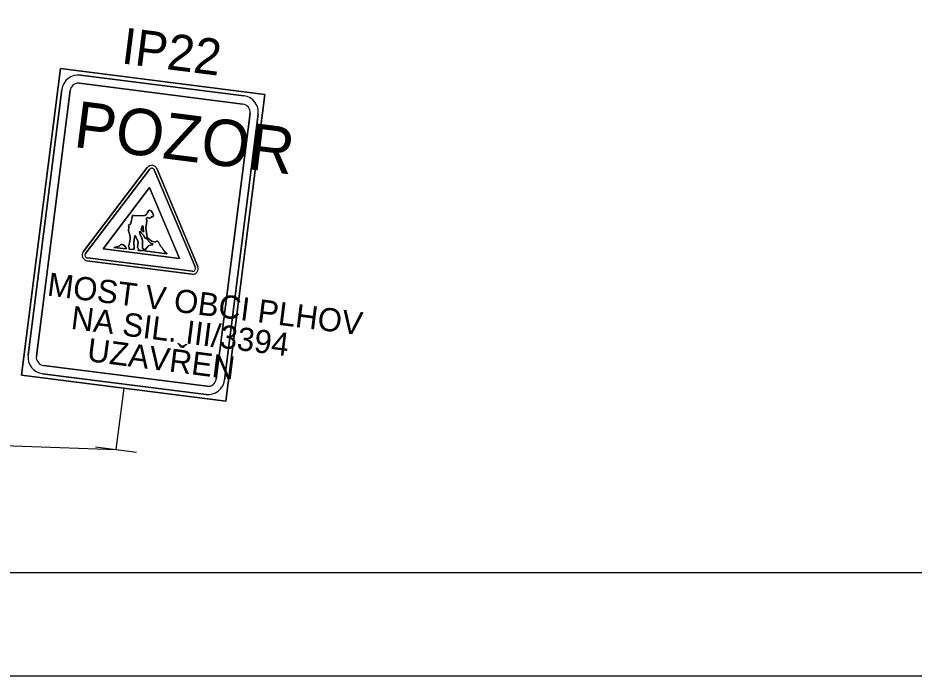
# Model space of a CAD drawing. Extents: x -688893 to -679983, y -1088371 to -1075771.
# Drawn here: x -685743 to -684438, y -1088371 to -1087413 of the extents above; entities that cross this region are included whole.
import ezdxf

# ---------------------------------------------------------------- set-up
doc = ezdxf.new("R2010")
doc.units = 0
for name, color, linetype in [('ramecek', 7, 'Continuous'), ('SDZ', 7, 'Continuous'), ('SDZ ozn', 7, 'Continuous'), ('SDZ plochy', 7, 'Continuous'), ('SDZ symbol', 7, 'Continuous')]:
    doc.layers.add(name, color=color, linetype=linetype)

msp = doc.modelspace()

# ---------------------------------------------------------------- linework, layer by layer
at = {"layer": 'ramecek'}
for points in [[(-679983.4, -1075770.7), (-679983.4, -1088370.7), (-688893.4, -1088370.7), (-688893.4, -1075770.7)], [(-680133.4, -1076070.7), (-680133.4, -1088220.7), (-688743.4, -1088220.7), (-688743.4, -1076070.7)]]:
    msp.add_lwpolyline(points, close=True, dxfattribs=at)
at = {"layer": 'SDZ'}
for p, q in [((-685737.5, -1087932.7), (-685680.8, -1087486.3)), ((-685680.8, -1087486.3), (-685383.2, -1087524.1)), ((-685651.8, -1087496), (-685413.7, -1087526.3)), ((-685727.8, -1087903.7), (-685678.7, -1087516.8)), ((-685715.9, -1087905.2), (-685666.8, -1087518.3)), ((-685653.3, -1087507.9), (-685415.3, -1087538.2)), ((-685383.2, -1087524.1), (-685439.9, -1087970.5)), ((-685404.9, -1087551.6), (-685454, -1087938.5)), ((-685393, -1087553.1), (-685442.1, -1087940)), ((-685647.6, -1087753.3), (-685554.4, -1087630.5)), ((-685551.2, -1087633.2), (-685644.4, -1087755.7)), ((-685551.1, -1087633.1), (-685551.1, -1087633.1)), ((-685484.5, -1087776), (-685544.2, -1087634)), ((-685540.4, -1087632.2), (-685480.8, -1087774.5)), ((-685540.4, -1087632.4), (-685540.4, -1087632.4)), ((-685551, -1087659.6), (-685618.8, -1087748.8)), ((-685507.6, -1087762.9), (-685551, -1087659.6)), ((-685575.8, -1087700.5), (-685578.4, -1087711.8)), ((-685574.3, -1087700.3), (-685575.8, -1087700.5)), ((-685560.7, -1087701), (-685574.3, -1087700.3)), ((-685557.8, -1087700.4), (-685560.7, -1087701)), ((-685555.5, -1087698.8), (-685557.8, -1087700.4)), ((-685554, -1087696), (-685555.5, -1087698.8)), ((-685552.2, -1087693.3), (-685554, -1087696)), ((-685550.5, -1087692.5), (-685552.2, -1087693.3)), ((-685548.6, -1087693.8), (-685550.5, -1087692.5)), ((-685549, -1087703.1), (-685547.8, -1087701.9)), ((-685546.7, -1087696.5), (-685548.6, -1087693.8)), ((-685547.8, -1087701.9), (-685546.8, -1087702.2)), ((-685546.8, -1087702.2), (-685545.7, -1087701.7)), ((-685545.3, -1087699.7), (-685546.7, -1087696.5)), ((-685545.7, -1087701.7), (-685545.3, -1087699.7)), ((-685578.4, -1087711.8), (-685581.7, -1087714.9)), ((-685581.7, -1087714.9), (-685581.1, -1087716.4)), ((-685556.4, -1087718.1), (-685555.8, -1087711.9)), ((-685555.8, -1087711.9), (-685555.3, -1087708)), ((-685555.7, -1087704.5), (-685554.7, -1087703.4)), ((-685555.4, -1087705.6), (-685555.7, -1087704.5)), ((-685555.3, -1087708), (-685555.4, -1087705.6)), ((-685554.7, -1087703.4), (-685553.9, -1087703.5)), ((-685553.9, -1087703.5), (-685552.4, -1087704.3)), ((-685552.4, -1087704.3), (-685550.5, -1087704.2)), ((-685550.5, -1087704.2), (-685549, -1087703.1)), ((-685581.1, -1087716.4), (-685582, -1087722.6)), ((-685582, -1087722.6), (-685581, -1087725.8)), ((-685581, -1087725.8), (-685579.6, -1087730.9)), ((-685565.6, -1087723.7), (-685565.2, -1087723.3)), ((-685564.8, -1087728.3), (-685565.6, -1087723.7)), ((-685565.2, -1087723.3), (-685560.2, -1087728.9)), ((-685563.1, -1087719.3), (-685563.4, -1087720.7)), ((-685563.4, -1087720.7), (-685562.6, -1087722.4)), ((-685562, -1087715.8), (-685563.1, -1087719.3)), ((-685562.6, -1087722.4), (-685560.2, -1087724.4)), ((-685561.1, -1087715.3), (-685562, -1087715.8)), ((-685560.6, -1087716.3), (-685561.1, -1087715.3)), ((-685560.4, -1087719.4), (-685560.6, -1087716.3)), ((-685560, -1087722.8), (-685560.4, -1087719.4)), ((-685560.2, -1087724.4), (-685560, -1087722.8)), ((-685555.7, -1087725.5), (-685556.4, -1087718.1)), ((-685554.9, -1087729.1), (-685555.7, -1087725.5)), ((-685580.4, -1087740.4), (-685581.9, -1087745.9)), ((-685579.6, -1087735.4), (-685580.4, -1087740.4)), ((-685579.6, -1087730.9), (-685579.6, -1087735.4)), ((-685574.1, -1087738.5), (-685573.3, -1087732.5)), ((-685573.7, -1087748.2), (-685574.1, -1087738.5)), ((-685573.3, -1087732.5), (-685572.5, -1087729.5)), ((-685572.5, -1087729.5), (-685570.4, -1087732.5)), ((-685570.4, -1087732.5), (-685568.3, -1087737.8)), ((-685567.6, -1087739.3), (-685568.6, -1087746.8)), ((-685568.3, -1087737.8), (-685567.6, -1087739.3)), ((-685562.3, -1087733.1), (-685564.8, -1087728.3)), ((-685561.5, -1087737.5), (-685562.3, -1087733.1)), ((-685561.6, -1087743), (-685561.5, -1087737.5)), ((-685560.2, -1087728.9), (-685559.2, -1087730.8)), ((-685559.2, -1087730.8), (-685557.7, -1087733.5)), ((-685557.7, -1087733.5), (-685556.1, -1087733.7)), ((-685556.1, -1087733.7), (-685549.7, -1087740.8)), ((-685554.5, -1087730.8), (-685554.9, -1087729.1)), ((-685554.9, -1087732), (-685554.5, -1087730.8)), ((-685548.3, -1087737.9), (-685554.9, -1087732)), ((-685549.7, -1087740.8), (-685546.3, -1087741.8)), ((-685542.7, -1087739), (-685548.3, -1087737.9)), ((-685540.9, -1087737.8), (-685542.7, -1087739)), ((-685539.7, -1087737.6), (-685540.9, -1087737.8)), ((-685538.2, -1087739.4), (-685539.7, -1087737.6)), ((-685536.6, -1087742.3), (-685538.2, -1087739.4)), ((-685618.8, -1087748.8), (-685507.6, -1087762.9)), ((-685598.7, -1087745.8), (-685603.3, -1087747.1)), ((-685603.3, -1087747.1), (-685584.8, -1087749)), ((-685595.5, -1087745), (-685598.7, -1087745.8)), ((-685592.8, -1087742.7), (-685595.5, -1087745)), ((-685591.7, -1087742.4), (-685592.8, -1087742.7)), ((-685590.5, -1087742.6), (-685591.7, -1087742.4)), ((-685589.6, -1087743.3), (-685590.5, -1087742.6)), ((-685586.9, -1087745.1), (-685589.6, -1087743.3)), ((-685585.8, -1087747.2), (-685586.9, -1087745.1)), ((-685584.8, -1087749), (-685585.8, -1087747.2)), ((-685581.9, -1087745.9), (-685580.9, -1087747.2)), ((-685580.9, -1087747.2), (-685580.9, -1087749.3)), ((-685580.9, -1087749.3), (-685574.3, -1087749.9)), ((-685574.3, -1087749.9), (-685573.7, -1087748.2)), ((-685568.6, -1087746.8), (-685567.5, -1087747.9)), ((-685567.4, -1087749), (-685567.7, -1087751.2)), ((-685567.7, -1087751.2), (-685560, -1087751.5)), ((-685567.5, -1087747.9), (-685567.4, -1087749)), ((-685561.3, -1087747.7), (-685561.6, -1087743)), ((-685559.4, -1087748.7), (-685561.3, -1087747.7)), ((-685560, -1087751.5), (-685559.4, -1087750)), ((-685559.4, -1087750), (-685559.4, -1087748.7)), ((-685555.9, -1087748.4), (-685558.6, -1087751.9)), ((-685558.6, -1087751.9), (-685526.1, -1087756.2)), ((-685552.8, -1087744.7), (-685555.9, -1087748.4)), ((-685550.2, -1087743.6), (-685552.8, -1087744.7)), ((-685546.9, -1087743.2), (-685550.2, -1087743.6)), ((-685546.3, -1087741.8), (-685546.9, -1087743.2)), ((-685534.7, -1087745.6), (-685536.6, -1087742.3)), ((-685532.4, -1087747.9), (-685534.7, -1087745.6)), ((-685531.3, -1087750.5), (-685532.4, -1087747.9)), ((-685529.8, -1087751.7), (-685531.3, -1087750.5)), ((-685528.4, -1087753.7), (-685529.8, -1087751.7)), ((-685526.7, -1087754.5), (-685528.4, -1087753.7)), ((-685642.2, -1087766.2), (-685489.3, -1087785.6)), ((-685641.7, -1087762.2), (-685488.8, -1087781.6)), ((-685526.1, -1087756.2), (-685526.7, -1087754.5)), ((-685467.4, -1087948.9), (-685705.5, -1087918.6)), ((-685439.9, -1087970.5), (-685737.5, -1087932.7)), ((-685468.9, -1087960.8), (-685707, -1087930.6)), ((-685588.7, -1087951.6), (-685600.1, -1088040.9)), ((-685629.8, -1088037.1), (-685570.3, -1088044.7))]:
    msp.add_line(p, q, dxfattribs=at)
msp.add_lwpolyline([(-686579.3, -1088005.8), (-685600.1, -1088040.9)], dxfattribs=at)
for centre, radius, start, end in [((-685654.9, -1087519.9), 24, 82.7618, 172.7618), ((-685654.9, -1087519.9), 12, 82.7618, 172.7618), ((-685416.8, -1087550.1), 24, 352.7618, 82.7618), ((-685416.8, -1087550.1), 12, 352.7618, 82.7618), ((-685547.9, -1087635.4), 8.1, 22.7309, 142.7927), ((-685547.9, -1087635.6), 4.05, 22.7961, 142.7275), ((-685641.1, -1087758.2), 8.1, 142.7927, 262.7618), ((-685641.2, -1087758.2), 4.05, 142.7275, 262.7618), ((-685488.3, -1087777.6), 8.1, 262.7618, 22.7309), ((-685488.3, -1087777.6), 4.05, 262.7618, 22.7961), ((-685704, -1087906.7), 24, 172.7618, 262.7618), ((-685704, -1087906.7), 12, 172.7618, 262.7618), ((-685465.9, -1087937), 24, 262.7618, 352.7618), ((-685465.9, -1087937), 12, 262.7618, 352.7618)]:
    msp.add_arc(centre, radius, start, end, dxfattribs=at)
at = {"layer": 'SDZ plochy'}
for p, q in [((-685680.8, -1087486.3), (-685737.5, -1087932.7)), ((-685383.2, -1087524.1), (-685680.8, -1087486.3)), ((-685413.7, -1087526.3), (-685651.8, -1087496)), ((-685651.8, -1087496), (-685413.7, -1087526.3)), ((-685678.7, -1087516.8), (-685727.8, -1087903.7)), ((-685727.8, -1087903.7), (-685678.7, -1087516.8)), ((-685715.9, -1087905.2), (-685666.8, -1087518.3)), ((-685666.8, -1087518.3), (-685715.9, -1087905.2)), ((-685653.3, -1087507.9), (-685415.3, -1087538.2)), ((-685415.3, -1087538.2), (-685653.3, -1087507.9)), ((-685439.9, -1087970.5), (-685383.2, -1087524.1)), ((-685404.9, -1087551.6), (-685454, -1087938.5)), ((-685454, -1087938.5), (-685404.9, -1087551.6)), ((-685442.1, -1087940), (-685393, -1087553.1)), ((-685393, -1087553.1), (-685442.1, -1087940)), ((-685647.6, -1087753.3), (-685554.4, -1087630.5)), ((-685554.4, -1087630.5), (-685647.6, -1087753.3)), ((-685551.2, -1087633.2), (-685644.4, -1087755.7)), ((-685644.4, -1087755.7), (-685551.2, -1087633.2)), ((-685484.5, -1087776), (-685544.2, -1087634)), ((-685544.2, -1087634), (-685484.5, -1087776)), ((-685540.4, -1087632.2), (-685480.8, -1087774.5)), ((-685480.8, -1087774.5), (-685540.4, -1087632.2)), ((-685618.8, -1087748.8), (-685551, -1087659.6)), ((-685551, -1087659.6), (-685618.8, -1087748.8)), ((-685551, -1087659.6), (-685507.6, -1087762.9)), ((-685507.6, -1087762.9), (-685551, -1087659.6)), ((-685575.8, -1087700.5), (-685578.4, -1087711.8)), ((-685578.4, -1087711.8), (-685575.8, -1087700.5)), ((-685574.3, -1087700.3), (-685575.8, -1087700.5)), ((-685575.8, -1087700.5), (-685574.3, -1087700.3)), ((-685560.7, -1087701), (-685574.3, -1087700.3)), ((-685574.3, -1087700.3), (-685560.7, -1087701)), ((-685557.8, -1087700.4), (-685560.7, -1087701)), ((-685560.7, -1087701), (-685557.8, -1087700.4)), ((-685555.5, -1087698.8), (-685557.8, -1087700.4)), ((-685557.8, -1087700.4), (-685555.5, -1087698.8)), ((-685554, -1087696), (-685555.5, -1087698.8)), ((-685555.5, -1087698.8), (-685554, -1087696)), ((-685552.2, -1087693.3), (-685554, -1087696)), ((-685554, -1087696), (-685552.2, -1087693.3)), ((-685550.5, -1087692.5), (-685552.2, -1087693.3)), ((-685552.2, -1087693.3), (-685550.5, -1087692.5)), ((-685548.6, -1087693.8), (-685550.5, -1087692.5)), ((-685550.5, -1087692.5), (-685548.6, -1087693.8)), ((-685549, -1087703.1), (-685547.8, -1087701.9)), ((-685547.8, -1087701.9), (-685549, -1087703.1)), ((-685546.7, -1087696.5), (-685548.6, -1087693.8)), ((-685548.6, -1087693.8), (-685546.7, -1087696.5)), ((-685547.8, -1087701.9), (-685546.8, -1087702.2)), ((-685546.8, -1087702.2), (-685547.8, -1087701.9)), ((-685546.8, -1087702.2), (-685545.7, -1087701.7)), ((-685545.7, -1087701.7), (-685546.8, -1087702.2)), ((-685545.3, -1087699.7), (-685546.7, -1087696.5)), ((-685546.7, -1087696.5), (-685545.3, -1087699.7)), ((-685545.7, -1087701.7), (-685545.3, -1087699.7)), ((-685545.3, -1087699.7), (-685545.7, -1087701.7)), ((-685578.4, -1087711.8), (-685581.7, -1087714.9)), ((-685581.7, -1087714.9), (-685578.4, -1087711.8)), ((-685581.7, -1087714.9), (-685581.1, -1087716.4)), ((-685581.1, -1087716.4), (-685581.7, -1087714.9)), ((-685556.4, -1087718.1), (-685555.8, -1087711.9)), ((-685555.8, -1087711.9), (-685556.4, -1087718.1)), ((-685555.8, -1087711.9), (-685555.3, -1087708)), ((-685555.3, -1087708), (-685555.8, -1087711.9)), ((-685555.7, -1087704.5), (-685554.7, -1087703.4)), ((-685554.7, -1087703.4), (-685555.7, -1087704.5)), ((-685555.4, -1087705.6), (-685555.7, -1087704.5)), ((-685555.7, -1087704.5), (-685555.4, -1087705.6)), ((-685555.3, -1087708), (-685555.4, -1087705.6)), ((-685555.4, -1087705.6), (-685555.3, -1087708)), ((-685554.7, -1087703.4), (-685553.9, -1087703.5)), ((-685553.9, -1087703.5), (-685554.7, -1087703.4)), ((-685553.9, -1087703.5), (-685552.4, -1087704.3)), ((-685552.4, -1087704.3), (-685553.9, -1087703.5)), ((-685552.4, -1087704.3), (-685550.5, -1087704.2)), ((-685550.5, -1087704.2), (-685552.4, -1087704.3)), ((-685550.5, -1087704.2), (-685549, -1087703.1)), ((-685549, -1087703.1), (-685550.5, -1087704.2)), ((-685581.1, -1087716.4), (-685582, -1087722.6)), ((-685582, -1087722.6), (-685581.1, -1087716.4)), ((-685582, -1087722.6), (-685581, -1087725.8)), ((-685581, -1087725.8), (-685582, -1087722.6)), ((-685581, -1087725.8), (-685579.6, -1087730.9)), ((-685579.6, -1087730.9), (-685581, -1087725.8)), ((-685565.6, -1087723.7), (-685565.2, -1087723.3)), ((-685565.2, -1087723.3), (-685565.6, -1087723.7)), ((-685564.8, -1087728.3), (-685565.6, -1087723.7)), ((-685565.6, -1087723.7), (-685564.8, -1087728.3)), ((-685565.2, -1087723.3), (-685560.2, -1087728.9)), ((-685560.2, -1087728.9), (-685565.2, -1087723.3)), ((-685563.4, -1087720.7), (-685563.1, -1087719.3)), ((-685563.1, -1087719.3), (-685563.4, -1087720.7)), ((-685562.6, -1087722.4), (-685563.4, -1087720.7)), ((-685563.4, -1087720.7), (-685562.6, -1087722.4)), ((-685563.1, -1087719.3), (-685562, -1087715.8)), ((-685562, -1087715.8), (-685563.1, -1087719.3)), ((-685560.2, -1087724.4), (-685562.6, -1087722.4)), ((-685562.6, -1087722.4), (-685560.2, -1087724.4)), ((-685562, -1087715.8), (-685561.1, -1087715.3)), ((-685561.1, -1087715.3), (-685562, -1087715.8)), ((-685561.1, -1087715.3), (-685560.6, -1087716.3)), ((-685560.6, -1087716.3), (-685561.1, -1087715.3)), ((-685560.6, -1087716.3), (-685560.4, -1087719.4)), ((-685560.4, -1087719.4), (-685560.6, -1087716.3)), ((-685560.4, -1087719.4), (-685560, -1087722.8)), ((-685560, -1087722.8), (-685560.4, -1087719.4)), ((-685560, -1087722.8), (-685560.2, -1087724.4)), ((-685560.2, -1087724.4), (-685560, -1087722.8)), ((-685555.7, -1087725.5), (-685556.4, -1087718.1)), ((-685556.4, -1087718.1), (-685555.7, -1087725.5)), ((-685554.9, -1087729.1), (-685555.7, -1087725.5)), ((-685555.7, -1087725.5), (-685554.9, -1087729.1)), ((-685580.4, -1087740.4), (-685581.9, -1087745.9)), ((-685581.9, -1087745.9), (-685580.4, -1087740.4)), ((-685579.6, -1087735.4), (-685580.4, -1087740.4)), ((-685580.4, -1087740.4), (-685579.6, -1087735.4)), ((-685579.6, -1087730.9), (-685579.6, -1087735.4)), ((-685579.6, -1087735.4), (-685579.6, -1087730.9)), ((-685574.1, -1087738.5), (-685573.3, -1087732.5)), ((-685573.3, -1087732.5), (-685574.1, -1087738.5)), ((-685573.7, -1087748.2), (-685574.1, -1087738.5)), ((-685574.1, -1087738.5), (-685573.7, -1087748.2)), ((-685573.3, -1087732.5), (-685572.5, -1087729.5)), ((-685572.5, -1087729.5), (-685573.3, -1087732.5)), ((-685572.5, -1087729.5), (-685570.4, -1087732.5)), ((-685570.4, -1087732.5), (-685572.5, -1087729.5)), ((-685570.4, -1087732.5), (-685568.3, -1087737.8)), ((-685568.3, -1087737.8), (-685570.4, -1087732.5)), ((-685567.6, -1087739.3), (-685568.6, -1087746.8)), ((-685568.6, -1087746.8), (-685567.6, -1087739.3)), ((-685568.3, -1087737.8), (-685567.6, -1087739.3)), ((-685567.6, -1087739.3), (-685568.3, -1087737.8)), ((-685562.3, -1087733.1), (-685564.8, -1087728.3)), ((-685564.8, -1087728.3), (-685562.3, -1087733.1)), ((-685561.5, -1087737.5), (-685562.3, -1087733.1)), ((-685562.3, -1087733.1), (-685561.5, -1087737.5)), ((-685561.6, -1087743), (-685561.5, -1087737.5)), ((-685561.5, -1087737.5), (-685561.6, -1087743)), ((-685560.2, -1087728.9), (-685559.2, -1087730.8)), ((-685559.2, -1087730.8), (-685560.2, -1087728.9)), ((-685559.2, -1087730.8), (-685557.7, -1087733.5)), ((-685557.7, -1087733.5), (-685559.2, -1087730.8)), ((-685557.7, -1087733.5), (-685556.1, -1087733.7)), ((-685556.1, -1087733.7), (-685557.7, -1087733.5)), ((-685556.1, -1087733.7), (-685549.7, -1087740.8)), ((-685549.7, -1087740.8), (-685556.1, -1087733.7)), ((-685554.5, -1087730.8), (-685554.9, -1087729.1)), ((-685554.9, -1087729.1), (-685554.5, -1087730.8)), ((-685554.9, -1087732), (-685554.5, -1087730.8)), ((-685554.5, -1087730.8), (-685554.9, -1087732)), ((-685548.3, -1087737.9), (-685554.9, -1087732)), ((-685554.9, -1087732), (-685548.3, -1087737.9)), ((-685549.7, -1087740.8), (-685546.3, -1087741.8)), ((-685546.3, -1087741.8), (-685549.7, -1087740.8)), ((-685542.7, -1087739), (-685548.3, -1087737.9)), ((-685548.3, -1087737.9), (-685542.7, -1087739)), ((-685540.9, -1087737.8), (-685542.7, -1087739)), ((-685542.7, -1087739), (-685540.9, -1087737.8)), ((-685539.7, -1087737.6), (-685540.9, -1087737.8)), ((-685540.9, -1087737.8), (-685539.7, -1087737.6)), ((-685538.2, -1087739.4), (-685539.7, -1087737.6)), ((-685539.7, -1087737.6), (-685538.2, -1087739.4)), ((-685536.6, -1087742.3), (-685538.2, -1087739.4)), ((-685538.2, -1087739.4), (-685536.6, -1087742.3)), ((-685507.6, -1087762.9), (-685618.8, -1087748.8)), ((-685618.8, -1087748.8), (-685507.6, -1087762.9)), ((-685598.7, -1087745.8), (-685603.3, -1087747.1)), ((-685603.3, -1087747.1), (-685598.7, -1087745.8)), ((-685603.3, -1087747.1), (-685584.8, -1087749)), ((-685584.8, -1087749), (-685603.3, -1087747.1)), ((-685595.5, -1087745), (-685598.7, -1087745.8)), ((-685598.7, -1087745.8), (-685595.5, -1087745)), ((-685592.8, -1087742.7), (-685595.5, -1087745)), ((-685595.5, -1087745), (-685592.8, -1087742.7)), ((-685591.7, -1087742.4), (-685592.8, -1087742.7)), ((-685592.8, -1087742.7), (-685591.7, -1087742.4)), ((-685590.5, -1087742.6), (-685591.7, -1087742.4)), ((-685591.7, -1087742.4), (-685590.5, -1087742.6)), ((-685589.6, -1087743.3), (-685590.5, -1087742.6)), ((-685590.5, -1087742.6), (-685589.6, -1087743.3)), ((-685586.9, -1087745.1), (-685589.6, -1087743.3)), ((-685589.6, -1087743.3), (-685586.9, -1087745.1)), ((-685585.8, -1087747.2), (-685586.9, -1087745.1)), ((-685586.9, -1087745.1), (-685585.8, -1087747.2)), ((-685584.8, -1087749), (-685585.8, -1087747.2)), ((-685585.8, -1087747.2), (-685584.8, -1087749)), ((-685581.9, -1087745.9), (-685580.9, -1087747.2)), ((-685580.9, -1087747.2), (-685581.9, -1087745.9)), ((-685580.9, -1087747.2), (-685580.9, -1087749.3)), ((-685580.9, -1087749.3), (-685580.9, -1087747.2)), ((-685580.9, -1087749.3), (-685574.3, -1087749.9)), ((-685574.3, -1087749.9), (-685580.9, -1087749.3)), ((-685574.3, -1087749.9), (-685573.7, -1087748.2)), ((-685573.7, -1087748.2), (-685574.3, -1087749.9)), ((-685568.6, -1087746.8), (-685567.5, -1087747.9)), ((-685567.5, -1087747.9), (-685568.6, -1087746.8)), ((-685567.4, -1087749), (-685567.7, -1087751.2)), ((-685567.7, -1087751.2), (-685567.4, -1087749)), ((-685567.7, -1087751.2), (-685560, -1087751.5)), ((-685560, -1087751.5), (-685567.7, -1087751.2)), ((-685567.5, -1087747.9), (-685567.4, -1087749)), ((-685567.4, -1087749), (-685567.5, -1087747.9)), ((-685561.3, -1087747.7), (-685561.6, -1087743)), ((-685561.6, -1087743), (-685561.3, -1087747.7)), ((-685559.4, -1087748.7), (-685561.3, -1087747.7)), ((-685561.3, -1087747.7), (-685559.4, -1087748.7)), ((-685560, -1087751.5), (-685559.4, -1087750)), ((-685559.4, -1087750), (-685560, -1087751.5)), ((-685559.4, -1087750), (-685559.4, -1087748.7)), ((-685559.4, -1087748.7), (-685559.4, -1087750)), ((-685555.9, -1087748.4), (-685558.6, -1087751.9)), ((-685558.6, -1087751.9), (-685555.9, -1087748.4)), ((-685558.6, -1087751.9), (-685526.1, -1087756.2)), ((-685526.1, -1087756.2), (-685558.6, -1087751.9)), ((-685552.8, -1087744.7), (-685555.9, -1087748.4)), ((-685555.9, -1087748.4), (-685552.8, -1087744.7)), ((-685550.2, -1087743.6), (-685552.8, -1087744.7)), ((-685552.8, -1087744.7), (-685550.2, -1087743.6)), ((-685546.9, -1087743.2), (-685550.2, -1087743.6)), ((-685550.2, -1087743.6), (-685546.9, -1087743.2)), ((-685546.3, -1087741.8), (-685546.9, -1087743.2)), ((-685546.9, -1087743.2), (-685546.3, -1087741.8)), ((-685534.7, -1087745.6), (-685536.6, -1087742.3)), ((-685536.6, -1087742.3), (-685534.7, -1087745.6)), ((-685532.4, -1087747.9), (-685534.7, -1087745.6)), ((-685534.7, -1087745.6), (-685532.4, -1087747.9)), ((-685531.3, -1087750.5), (-685532.4, -1087747.9)), ((-685532.4, -1087747.9), (-685531.3, -1087750.5)), ((-685529.8, -1087751.7), (-685531.3, -1087750.5)), ((-685531.3, -1087750.5), (-685529.8, -1087751.7)), ((-685528.4, -1087753.7), (-685529.8, -1087751.7)), ((-685529.8, -1087751.7), (-685528.4, -1087753.7)), ((-685526.7, -1087754.5), (-685528.4, -1087753.7)), ((-685528.4, -1087753.7), (-685526.7, -1087754.5)), ((-685489.3, -1087785.6), (-685642.2, -1087766.2)), ((-685642.2, -1087766.2), (-685489.3, -1087785.6)), ((-685641.7, -1087762.2), (-685488.8, -1087781.6)), ((-685488.8, -1087781.6), (-685641.7, -1087762.2)), ((-685526.1, -1087756.2), (-685526.7, -1087754.5)), ((-685526.7, -1087754.5), (-685526.1, -1087756.2)), ((-685467.4, -1087948.9), (-685705.5, -1087918.6)), ((-685705.5, -1087918.6), (-685467.4, -1087948.9)), ((-685737.5, -1087932.7), (-685439.9, -1087970.5)), ((-685707, -1087930.6), (-685468.9, -1087960.8)), ((-685468.9, -1087960.8), (-685707, -1087930.6))]:
    msp.add_line(p, q, dxfattribs=at)
for centre, radius, start, end in [((-685654.9, -1087519.9), 24, 82.7618, 172.7618), ((-685654.9, -1087519.9), 24, 82.7618, 172.7618), ((-685654.9, -1087519.9), 12, 82.7618, 172.7618), ((-685654.9, -1087519.9), 12, 82.7618, 172.7618), ((-685416.8, -1087550.1), 24, 352.7618, 82.7618), ((-685416.8, -1087550.1), 24, 352.7618, 82.7618), ((-685416.8, -1087550.1), 12, 352.7618, 82.7618), ((-685416.8, -1087550.1), 12, 352.7618, 82.7618), ((-685547.9, -1087635.4), 8.1, 22.7309, 142.7927), ((-685547.9, -1087635.4), 8.1, 22.7309, 142.7927), ((-685547.9, -1087635.6), 4.05, 22.7961, 142.7275), ((-685547.9, -1087635.6), 4.05, 22.7961, 142.7275), ((-685641.1, -1087758.2), 8.1, 142.7927, 262.7618), ((-685641.1, -1087758.2), 8.1, 142.7927, 262.7618), ((-685641.2, -1087758.2), 4.05, 142.7275, 262.7618), ((-685641.2, -1087758.2), 4.05, 142.7275, 262.7618), ((-685488.3, -1087777.6), 8.1, 262.7618, 22.7309), ((-685488.3, -1087777.6), 8.1, 262.7618, 22.7309), ((-685488.3, -1087777.6), 4.05, 262.7618, 22.7961), ((-685488.3, -1087777.6), 4.05, 262.7618, 22.7961), ((-685704, -1087906.7), 24, 172.7618, 262.7618), ((-685704, -1087906.7), 24, 172.7618, 262.7618), ((-685704, -1087906.7), 12, 172.7618, 262.7618), ((-685704, -1087906.7), 12, 172.7618, 262.7618), ((-685465.9, -1087937), 24, 262.7618, 352.7618), ((-685465.9, -1087937), 24, 262.7618, 352.7618), ((-685465.9, -1087937), 12, 262.7618, 352.7618), ((-685465.9, -1087937), 12, 262.7618, 352.7618)]:
    msp.add_arc(centre, radius, start, end, dxfattribs=at)

# ---------------------------------------------------------------- texts
at = {"layer": 'SDZ ozn'}
msp.add_text('IP22', height=52.5, rotation=352.7618, dxfattribs=at).set_placement((-685593.6, -1087478.8))
at = {"layer": 'SDZ symbol'}
for s, height, p in [('POZOR', 67.5, (-685663.3, -1087600.4)), ('MOST V OBCI PLHOV', 33.75, (-685701.2, -1087816.7)), ('NA SIL. III/3394', 33.75, (-685666.7, -1087865.2)), ('UZAVŘEN', 33.75, (-685643.3, -1087912.2))]:
    msp.add_text(s, height=height, rotation=352.7618, dxfattribs=at).set_placement(p)

doc.saveas('drawing.dxf')
